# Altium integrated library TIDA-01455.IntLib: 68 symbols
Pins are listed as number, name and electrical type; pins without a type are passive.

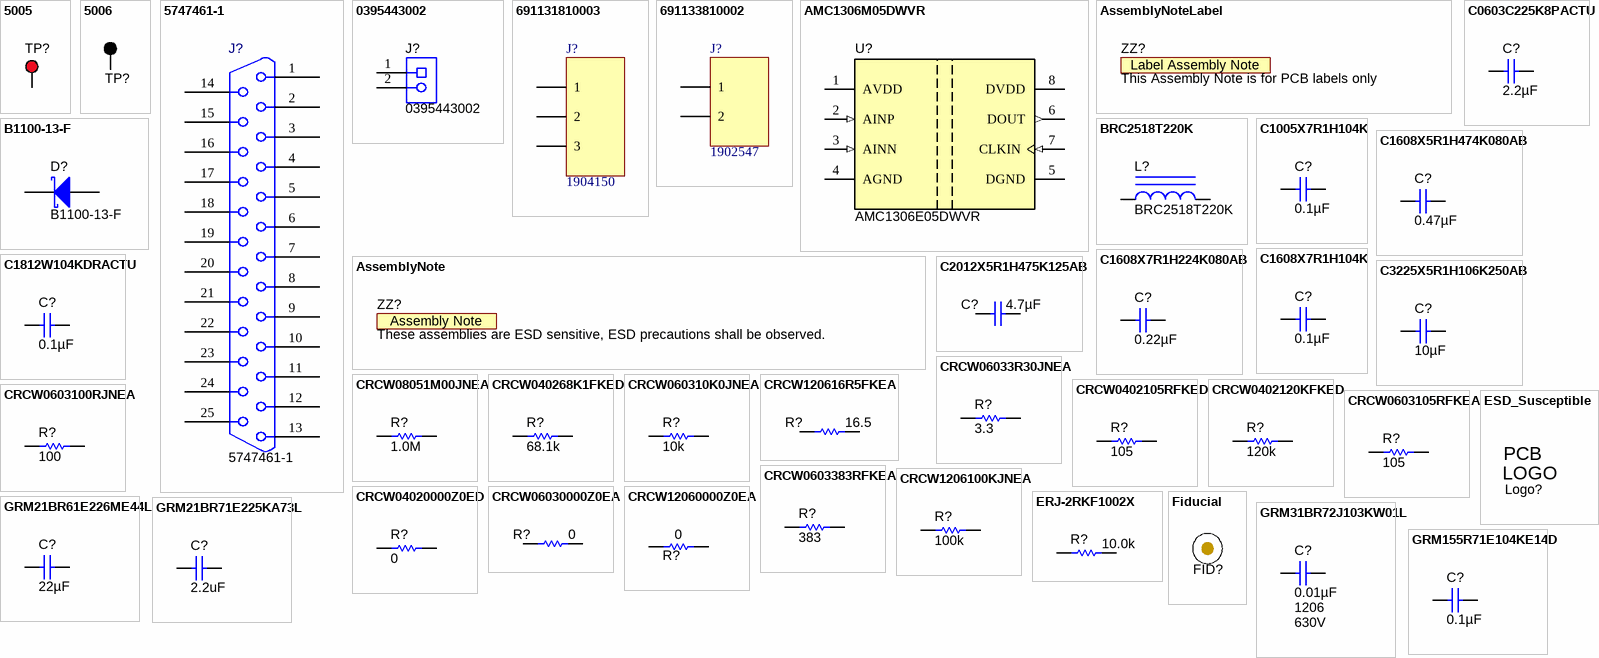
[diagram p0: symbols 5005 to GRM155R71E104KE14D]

## 5005
designator TP?  (value not drawn)
Test Point, Compact, Red, TH; Manufacturer: Keystone; CompType: Test Point Loop; ContactFinish: Silver
footprint Keystone5005
pins: 1

## 5006
designator TP?  (value not drawn)
Test Point, Compact, Black, TH; Manufacturer: Keystone; CompType: Test Point Loop; ContactFinish: Silver
footprint Keystone5006
pins: 1

## 5747461-1
designator J?
Connector, TH, DB25 parallel port, plastic, right angle; Manufacturer: AMP
footprint Amp_DB25 (Amp 5747461-1)
pins: 1, 2, 3, 4, 5, 6, 7, 8, 9, 10, 11, 12, 13, 14, 15, 16, 17, 18, 19, 20, 21, 22, 23, 24, 25

## 0395443002
designator J?
Terminal Block, 5.08mm, 2x1, TH; Manufacturer: Molex; SymbolCreator: a0412235; Pitch_mm: 5.08; Gender: Female; Row_Count: 1; Current_A: 15; Voltage_V: 300
footprint Molex_0395443002
pins: 1, 2

## 691131810003
designator J?, comment 1904150
Horizontal Cable Entry with Pressure Clamp, Serie 1318 - 10.00 mm; Manufacturer: Phoenix Contact; ComponentLink1 Description: Manufacturer; NoPins: 3
footprint PHOENIX_1902547 (CONN, PCB TERMINAL BLOCK, 9.52 MM PITCH, 3POS, TH)
pins: 1, 2, 3

## 691133810002
designator J?, comment 1902547
Horizontal Cable Entry with Pressure Clamp, Serie 1338 - 10.00 mm; Manufacturer: Phoenix Contact; ComponentLink1 Description: Manufacturer; ComponentLink2 Description: Datasheet; NoPins: 2
footprint PHOENIX_1902547 (CONN, PCB TERMINAL BLOCK, 9.52 MM PITCH, 2POS, TH)
pins: 1, 2

## AMC1306M05DWVR
designator U?, comment AMC1306E05DWVR
Small, High-Precision, Reinforced Isolated Delta-Sigma Modulator with Manchester Coded Output, DWV0008A; Alternate PartNumber: AMC1306M05DWV; Manufacturer: Texas Instruments; SymbolCreator: Altium; SizeArea_mm2: 67.275; SizeAreaWB_mm2: 105.975; SizeX_mm: 11.5; SizeY_mm: 5.85; SizeZ_mm: 2.8; CompType: IC; U/M: EA
footprint DWV0008A
pins: 1 AVDD (power), 2 AINP (in), 3 AINN (in), 4 AGND (power), 5 DGND (power), 6 DOUT (out), 7 CLKIN (in), 8 DVDD (power)

## AssemblyNote
designator ZZ?, comment These assemblies are ESD sensitive, ESD precautions shall be observed.  (no BOM)
SymbolCreator: codlsc; CompType: AssemblyNote
footprint AssemblyNote

## AssemblyNoteLabel
designator ZZ?, comment This Assembly Note is for PCB labels only  (no BOM)
SymbolCreator: a0412235
footprint AssemblyNoteLabel

## B1100-13-F
designator D?
Diode, Schottky, 100 V, 1 A, SMA; Manufacturer: Diodes Inc.; U/M: EA; Vf_V: 0.79; Value: 100V; Value1: 1A; Value2: 0.79V; Io_A: 1; Vr_V: 100; TJmax_C: 150; RJC_CperW: 25; AEC Category: Q101
signal-integrity model Diode
simulation model DI_B1100
footprint SMA
pins: 1 K, 2 A

## BRC2518T220K
designator L?
Inductor, Wirewound, 22 µH, 0.49 A, 0.56 ohm, SMD; Manufacturer: Taiyo Yuden; Value: 22uH; Ind_H: 22.0E-6; ValueDisplayed: 22µH; Imax_A: 0.49; Irms: 0.49A @ 40C rise; Isat: 0.64A @ 30% inductance drop; DCR_ohm: 0.56; Value2: 0.49A
signal-integrity model Inductor
simulation model Inductor
footprint 1007
pins: 1, 2

## C0603C225K8PACTU
designator C?  ValueDisplayed: 2.2µF  (hidden comment: C0603C225K8PACTU)
CAP, CERM, 2.2 µF, 10 V, +/- 10%, X5R, 0603; Manufacturer: Kemet; Polarized: N; CompType: Capacitor; Value: 2.2uF; U/M: EA; Cap_F: 0.0000022; Tolerance_%: 10; Value1: Unknown; Value2: 10V; TaMin_C: -55; TaMax_C: 85; Cap_Case: 0603; SizeArea_mm2: 1.28; SizeAreaWB_mm2: 4.68; SizeX_mm: 1.6; SizeY_mm: 0.8; SizeZ_mm: 1; AEC Category: Q200
signal-integrity model Cap
simulation model Cap
footprint 0603
footprint 0603M
footprint 0603L
footprint 0603_HV
footprint 0603S
pins: 1, 2

## C1005X7R1H104K
designator C?  ValueDisplayed: 0.1µF  (hidden comment: C1005X7R1H104K)
CAP, CERM, 0.1uF, 50V, +/-10%, C0G/NP0, 0402; Manufacturer: TDK; Polarized: N; CompType: Capacitor; U/M: EA; Cap_F: 0.0000001; Tolerance_%: 10; VDC_V: 50; TaMin_C: -55; TaMax_C: 125; Cap_Case: 0402
signal-integrity model Cap
simulation model Cap
footprint 0402
footprint 0402M
footprint 0402L
pins: 1, 2

## C1608X5R1H474K080AB
designator C?  ValueDisplayed: 0.47µF  (hidden comment: C1608X5R1H474K080AB)
CAP, CERM, 0.47 µF, 50 V, +/- 10%, X5R, 0603; Manufacturer: TDK; Polarized: N; CompType: Capacitor; Value: 0.47uF; U/M: EA; Cap_F: 0.00000047; Tolerance_%: 10; ESR_ohm: 0.010974; Value1: 0.010974 ohm; VDC_V: 50; Value2: 50V; IRMS_A: 1.57483; TaMin_C: -55; TaMax_C: 85; Cap_Case: 0603; AEC Category: Q200; SizeArea_mm2: 1.28; SizeAreaWB_mm2: 4.68; SizeX_mm: 1.6; SizeY_mm: 0.8; SizeZ_mm: 1
signal-integrity model Cap
simulation model Cap
footprint 0603
footprint 0603M
footprint 0603L
footprint 0603_HV
footprint 0603S
pins: 1, 2

## C1608X7R1H104K
designator C?  ValueDisplayed: 0.1µF  (hidden comment: C1608X7R1H104K)
CAP, CERM, 0.1 µF, 50 V, +/- 10%, X7R, 0603; Manufacturer: TDK; Polarized: N; CompType: Capacitor; Value: 0.1uF; U/M: EA; Cap_F: 0.0000001; Tolerance_%: 10; ESR_ohm: 0.017; Value1: 0.017 ohm; VDC_V: 50; Value2: 50V; TaMin_C: -55; TaMax_C: 125; Cap_Case: 0603; AEC Category: Q200
signal-integrity model Cap
simulation model Cap
footprint 0603
footprint 0603M
footprint 0603L
footprint 0603_HV
footprint 0603S
pins: 1, 2

## C1608X7R1H224K080AB
designator C?  ValueDisplayed: 0.22µF  (hidden comment: C1608X7R1H224K080AB)
CAP, CERM, 0.22 µF, 50 V, +/- 10%, X7R, 0603; Manufacturer: TDK; Polarized: N; CompType: Capacitor; Value: 0.22uF; U/M: EA; Cap_F: 0.00000022; Tolerance_%: 10; Value1: Unknown; VDC_V: 50; Value2: 50V; TaMin_C: -55; TaMax_C: 125; Cap_Case: 0603; AEC Category: Q200
signal-integrity model Cap
simulation model Cap
footprint 0603
footprint 0603M
footprint 0603L
footprint 0603_HV
footprint 0603S
pins: 1, 2

## C1812W104KDRACTU
designator C?  ValueDisplayed: 0.1µF  (hidden comment: C1812W104KDRACTU)
CAP, CERM, 0.1 µF, 1000 V, +/- 10%, X7R, 1812; Manufacturer: Kemet; Polarized: N; CompType: Capacitor; Value: 0.1uF; U/M: EA; Cap_F: 0.0000001; Tolerance_%: 10; Value1: Unknown; VDC_V: 1000; Value2: 1000V; TaMin_C: -55; TaMax_C: 125; Cap_Case: 1812; AEC Category: Q200
signal-integrity model Cap
simulation model Cap
footprint 1812_254
pins: 1, 2

## C2012X5R1H475K125AB
designator C?  ValueDisplayed: 4.7µF  (hidden comment: C2012X5R1H475K125AB)
CAP, CERM, 4.7 µF, 50 V, +/- 10%, X5R, 0805; Manufacturer: TDK; Polarized: N; CompType: Capacitor; Value: 4.7uF; U/M: EA; Cap_F: 0.0000047; Tolerance_%: 10; Value1: Unknown; VDC_V: 50; Value2: 50V; TaMin_C: -55; TaMax_C: 85; Cap_Case: 0805; AEC Category: Q200
signal-integrity model Cap
simulation model Cap
footprint 0805_HV
footprint 0805_HV1
footprint 0805
footprint 0805M
footprint 0805L
pins: 1, 2

## C3225X5R1H106K250AB
designator C?  ValueDisplayed: 10µF  (hidden comment: C3225X5R1H106K250AB)
CAP, CERM, 10 µF, 50 V, +/- 10%, X5R, 1210; Manufacturer: TDK; Polarized: N; CompType: Capacitor; Value: 10uF; U/M: EA; Cap_F: 0.00001; Tolerance_%: 10; Value1: Unknown; VDC_V: 50; Value2: 50V; TaMin_C: -55; TaMax_C: 85; Cap_Case: 1210; AEC Category: Q200
signal-integrity model Cap
simulation model Cap
footprint 1210_280
pins: 1, 2

## CRCW06033R30JNEA
designator R?  ValueDisplayed: 3.3  (hidden comment: CRCW06033R30JNEA)
RES, 3.3, 5%, 0.1 W, 0603; Manufacturer: Vishay-Dale; CompType: Resistor; Value: 3.3; Value_Code: 3R30; Tolerance_%: 5; Power_W: 0.1; Value2: 0.1W; VDC_V: 75; TempCo: 200 ppm/C; SizeArea_mm2: 1.28; SizeX_mm: 1.6; SizeY_mm: 0.8; SizeZ_mm: 1; EIA_Code: E24; U/M: EA; AEC Category: Q200
signal-integrity model Resistor
simulation model Resistor
footprint 0603
footprint 0603M
footprint 0603L
footprint 0603_HV
footprint 0603S
pins: 1, 2

## CRCW08051M00JNEA
designator R?  ValueDisplayed: 1.0M  (hidden comment: CRCW08051M00JNEA)
RES, 1.0 M, 5%, 0.125 W, 0805; Manufacturer: Vishay-Dale; CompType: Resistor; Value: 1.0Meg; Res_ohm: 1000000; Value_Code: 1M00; Tolerance_%: 5; Power_W: 0.125; Value2: 0.125W; VDC_V: 150; TempCo: 200 ppm/C; SizeArea_mm2: 2.5; SizeX_mm: 2; SizeY_mm: 1.25; SizeZ_mm: 1.45; EIA_Code: E24; U/M: EA; AEC Category: Q200
signal-integrity model Resistor
simulation model Resistor
footprint 0805_HV
footprint 0805_HV1
footprint 0805
footprint 0805M
footprint 0805L
pins: 1, 2

## CRCW040268K1FKED
designator R?  ValueDisplayed: 68.1k  (hidden comment: CRCW040268K1FKED)
RES, 68.1 k, 1%, 0.063 W, 0402; Manufacturer: Vishay-Dale; CompType: Resistor; Value: 68.1k; Res_ohm: 68100; Value_Code: 68k1; Tolerance_%: 1; Power_W: 0.063; Value2: 0.063W; VDC_V: 50; TempCo: 100 ppm/C; EIA_Code: E96; U/M: EA; AEC Category: Q200
signal-integrity model Resistor
simulation model Resistor
footprint 0402
footprint 0402M
footprint 0402L
footprint 0402S
pins: 1, 2

## CRCW060310K0JNEA
designator R?  ValueDisplayed: 10k  (hidden comment: CRCW060310K0JNEA)
RES, 10 k, 5%, 0.1 W, 0603; Manufacturer: Vishay-Dale; CompType: Resistor; Value: 10k; Res_ohm: 10000; Value_Code: 10k0; Tolerance_%: 5; Power_W: 0.1; Value2: 0.1W; VDC_V: 75; TempCo: 200 ppm/C; EIA_Code: E24; U/M: EA; AEC Category: Q200
signal-integrity model Resistor
simulation model Resistor
footprint 0603
footprint 0603M
footprint 0603L
footprint 0603_HV
footprint 0603S
pins: 1, 2

## CRCW120616R5FKEA
designator R?  ValueDisplayed: 16.5  (hidden comment: CRCW120616R5FKEA)
RES, 16.5, 1%, 0.25 W, 1206; Manufacturer: Vishay-Dale; CompType: Resistor; Value: 16.5; Value_Code: 16R5; Tolerance_%: 1; Power_W: 0.25; Value2: 0.25W; VDC_V: 200; TempCo: 100 ppm/C; EIA_Code: E96; U/M: EA; AEC Category: Q200; SizeArea_mm2: 5.12; SizeX_mm: 3.2; SizeY_mm: 1.6; SizeZ_mm: 1.35
signal-integrity model Resistor
simulation model Resistor
footprint 1206
footprint 1206M
footprint 1206L
pins: 1, 2

## CRCW0402105RFKED
designator R?  ValueDisplayed: 105  (hidden comment: CRCW0402105RFKED)
RES, 105, 1%, 0.063 W, 0402; Manufacturer: Vishay-Dale; CompType: Resistor; Value: 105; Value_Code: 105R; Tolerance_%: 1; Power_W: 0.063; Value2: 0.063W; VDC_V: 50; TempCo: 100 ppm/C; EIA_Code: E96; U/M: EA; AEC Category: Q200; SizeArea_mm2: 0.5; SizeZ_mm: 0.6
signal-integrity model Resistor
simulation model Resistor
footprint 0402
footprint 0402M
footprint 0402L
footprint 0402S
pins: 1, 2

## CRCW0402120KFKED
designator R?  ValueDisplayed: 120k  (hidden comment: CRCW0402120KFKED)
RES, 120 k, 1%, 0.063 W, 0402; Manufacturer: Vishay-Dale; CompType: Resistor; Value: 120k; Res_ohm: 120000; Tolerance_%: 1; Power_W: 0.063; Value2: 0.063W; VDC_V: 50; TempCo: 100 ppm/C; U/M: EA; AEC Category: Q200; SizeArea_mm2: 0.5; SizeZ_mm: 0.6
signal-integrity model Resistor
simulation model Resistor
footprint 0402
footprint 0402M
footprint 0402L
footprint 0402S
pins: 1, 2

## CRCW0603100RJNEA
designator R?  ValueDisplayed: 100  (hidden comment: CRCW0603100RJNEA)
RES, 100, 5%, 0.1 W, 0603; Manufacturer: Vishay-Dale; CompType: Resistor; Value: 100; Value_Code: 100R; Tolerance_%: 5; Power_W: 0.1; Value2: 0.1W; VDC_V: 75; TempCo: 200 ppm/C; SizeArea_mm2: 1.28; SizeX_mm: 1.6; SizeY_mm: 0.8; SizeZ_mm: 1; EIA_Code: E24; U/M: EA; AEC Category: Q200
signal-integrity model Resistor
simulation model Resistor
footprint 0603
footprint 0603M
footprint 0603L
footprint 0603_HV
footprint 0603S
pins: 1, 2

## CRCW0603105RFKEA
designator R?  ValueDisplayed: 105  (hidden comment: CRCW0603105RFKEA)
RES, 105, 1%, 0.1 W, 0603; Manufacturer: Vishay-Dale; CompType: Resistor; Value: 105; Value_Code: 105R; Tolerance_%: 1; Power_W: 0.1; Value2: 0.1W; VDC_V: 75; TempCo: 100 ppm/C; SizeArea_mm2: 1.28; SizeX_mm: 1.6; SizeY_mm: 0.8; EIA_Code: E96; U/M: EA; AEC Category: Q200
signal-integrity model Resistor
simulation model Resistor
footprint 0603
footprint 0603M
footprint 0603L
footprint 0603_HV
footprint 0603S
pins: 1, 2

## CRCW0603383RFKEA
designator R?  ValueDisplayed: 383  (hidden comment: CRCW0603383RFKEA)
RES, 383, 1%, 0.1 W, 0603; Manufacturer: Vishay-Dale; CompType: Resistor; Value: 383; Value_Code: 383R; Tolerance_%: 1; Power_W: 0.1; Value2: 0.1W; VDC_V: 75; TempCo: 100 ppm/C; SizeArea_mm2: 1.28; SizeX_mm: 1.6; SizeY_mm: 0.8; EIA_Code: E96; U/M: EA; AEC Category: Q200
signal-integrity model Resistor
simulation model Resistor
footprint 0603
footprint 0603M
footprint 0603L
footprint 0603_HV
footprint 0603S
pins: 1, 2

## CRCW1206100KJNEA
designator R?  ValueDisplayed: 100k  (hidden comment: CRCW1206100KJNEA)
RES, 100 k, 5%, 0.25 W, 1206; Manufacturer: Vishay-Dale; CompType: Resistor; Value: 100k; Res_ohm: 100000; Tolerance_%: 5; Power_W: 0.25; Value2: 0.25W; VDC_V: 200; TempCo: 200 ppm/C; EIA_Code: E24; U/M: EA; AEC Category: Q200
signal-integrity model Resistor
simulation model Resistor
footprint 1206
footprint 1206M
footprint 1206L
pins: 1, 2

## CRCW04020000Z0ED
designator R?  ValueDisplayed: 0  (hidden comment: CRCW04020000Z0ED)
RES, 0, 5%, 0.063 W, 0402; Manufacturer: Vishay-Dale; CompType: Resistor; Value: 0; Value_Code: 0000; Tolerance_%: 5; Power_W: 0.063; Value2: 0.063W; VDC_V: 50; TempCo: 200 ppm/C; EIA_Code: E24; U/M: EA; AEC Category: Q200; SizeArea_mm2: 0.5; SizeX_mm: 1; SizeZ_mm: 0.6
signal-integrity model Resistor
simulation model Resistor
footprint 0402
footprint 0402M
footprint 0402L
footprint 0402S
pins: 1, 2

## CRCW06030000Z0EA
designator R?  ValueDisplayed: 0  (hidden comment: CRCW06030000Z0EA)
RES, 0, 5%, 0.1 W, 0603; Manufacturer: Vishay-Dale; CompType: Resistor; Value: 0; Value_Code: 0000; Tolerance_%: 5; Power_W: 0.1; Value2: 0.1W; VDC_V: 75; TempCo: 200 ppm/C; EIA_Code: E24; U/M: EA; AEC Category: Q200; SizeArea_mm2: 1.28; SizeX_mm: 1.6; SizeY_mm: 0.8; SizeZ_mm: 1
signal-integrity model Resistor
simulation model Resistor
footprint 0603
footprint 0603M
footprint 0603L
footprint 0603_HV
footprint 0603S
pins: 1, 2

## CRCW12060000Z0EA
designator R?  ValueDisplayed: 0  (hidden comment: CRCW12060000Z0EA)
RES, 0, 5%, 0.25 W, 1206; Manufacturer: Vishay-Dale; CompType: Resistor; Value: 0; Value_Code: 0000; Tolerance_%: 5; Power_W: 0.25; Value2: 0.25W; VDC_V: 200; TempCo: 200 ppm/C; EIA_Code: E24; U/M: EA; AEC Category: Q200; SizeArea_mm2: 5.12; SizeX_mm: 3.2; SizeY_mm: 1.6; SizeZ_mm: 1.35
signal-integrity model Resistor
simulation model Resistor
footprint 1206
footprint 1206M
footprint 1206L
pins: 1, 2

## ERJ-2RKF1002X
designator R?  ValueDisplayed: 10.0k  (hidden comment: ERJ-2RKF1002X)
RES, 10.0 k, 1%, 0.1 W, 0402; Manufacturer: Panasonic; CompType: Resistor; Value: 10.0k; Res_ohm: 10000; Value_Code: 10k0; Tolerance_%: 1; Power_W: 0.1; Value2: 0.1W; VDC_V: 50; TempCo: 100 ppm/C; EIA_Code: E96; U/M: EA; AEC Category: Q200
signal-integrity model Resistor
simulation model Resistor
footprint 0402
footprint 0402M
footprint 0402L
footprint 0402S
pins: 1, 2

## ESD_Susceptible
designator Logo?, comment ESD Susceptible  (value not drawn)  (no BOM)
ESD Susceptible Symbol; SymbolCreator: a0412235
footprint ESD_Overlay_Large
footprint ESD_Overlay_Medium
footprint ESD_Overlay_Small

## Fiducial
designator FID?  (value not drawn)
Fiducial mark.  There is nothing to buy or mount.; SymbolCreator: codlsc
footprint Fiducial10-30
footprint Fiducial10-20
footprint Fiducial15-30
footprint Fiducial20-40
footprint Fiducial6.4-20

## GRM21BR61E226ME44L
designator C?  ValueDisplayed: 22µF  (hidden comment: GRM21BR61E226ME44L)
CAP, CERM, 22 µF, 25 V, +/- 20%, X5R, 0805; Manufacturer: MuRata; Polarized: N; CompType: Capacitor; Value: 22uF; U/M: EA; Cap_F: 0.000022; Tolerance_%: 20; Value1: Unknown; VDC_V: 25; Value2: 25V; TaMin_C: -55; TaMax_C: 85; Cap_Case: 0805; AEC Category: Q200
signal-integrity model Cap
simulation model Cap
footprint 0805_HV
footprint 0805_HV1
footprint 0805
footprint 0805M
footprint 0805L
pins: 1, 2

## GRM21BR71E225KA73L
designator C?  ValueDisplayed: 2.2uF  (hidden comment: GRM21BR71E225KA73L)
CAP, CERM, 2.2uF, 25V, +/-10%, X7R, 0805; Manufacturer: MuRata; Polarized: N; CompType: Capacitor; U/M: EA; Cap_F: 0.0000022; Tolerance_%: 10; ESR_Ohm: 0.005; Value1: 0.005 ohm; VDC_V: 25; TaMin_C: -55; TaMax_C: 125; Cap_Case: 0805
signal-integrity model Cap
simulation model Cap
footprint 0805_HV
footprint 0805
footprint 0805M
footprint 0805L
pins: 1, 2

## GRM31BR72J103KW01L
designator C?  ValueDisplayed: 0.01µF  PackageReference: 1206  Value2: 630V  (hidden comment: GRM31BR72J103KW01L)
CAP, CERM, 0.01uF, 630V, +/-10%, X7R, 1206; Manufacturer: MuRata; Polarized: N; CompType: Capacitor; U/M: EA; Cap_F: 0.00000001; Tolerance_%: 10; Value1: Unknown; VDC_V: 630; TaMin_C: -55; TaMax_C: 125
signal-integrity model Cap
simulation model Cap
footprint 1206
footprint 1206M
footprint 1206L
pins: 1, 2

## GRM155R71E104KE14D
designator C?  ValueDisplayed: 0.1µF  (hidden comment: GRM155R71E104KE14D)
CAP, CERM, 0.1 µF, 25 V, +/- 10%, X7R, 0402; Manufacturer: MuRata; Polarized: N; CompType: Capacitor; Value: 0.1uF; U/M: EA; Cap_F: 0.0000001; Tolerance_%: 10; Value1: Unknown; VDC_V: 25; Value2: 25V; TaMin_C: -55; TaMax_C: 125; Cap_Case: 0402; AEC Category: Q200
signal-integrity model Cap
simulation model Cap
footprint 0402
footprint 0402M
footprint 0402L
footprint 0402S
pins: 1, 2

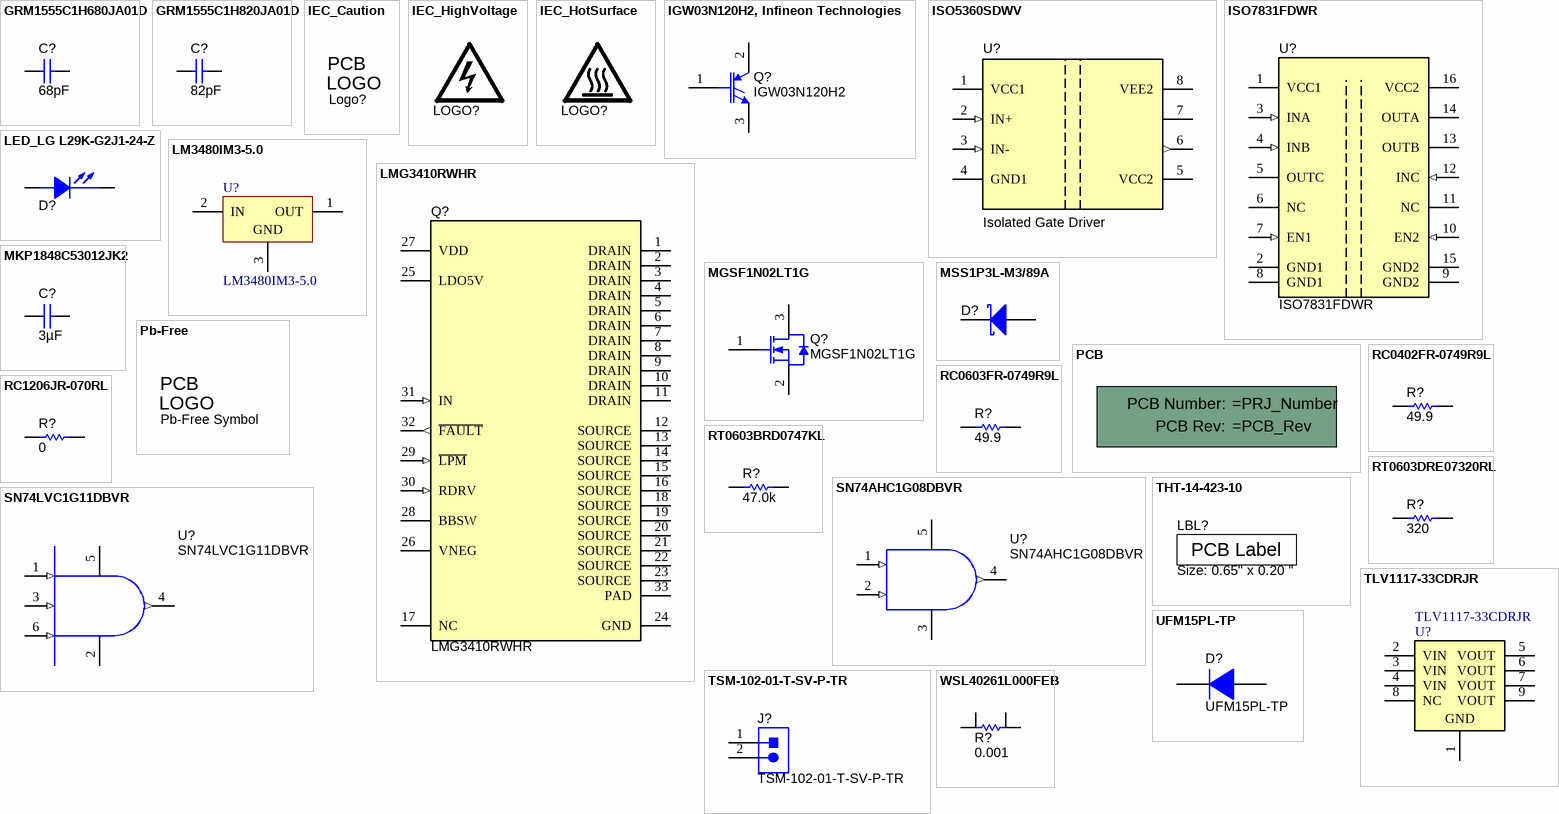
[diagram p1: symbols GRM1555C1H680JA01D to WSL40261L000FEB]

## GRM1555C1H680JA01D
designator C?  ValueDisplayed: 68pF  (hidden comment: GRM1555C1H680JA01D)
CAP, CERM, 68 pF, 50 V, +/- 5%, C0G/NP0, 0402; Manufacturer: MuRata; Polarized: N; CompType: Capacitor; Value: 68pF; U/M: EA; Cap_F: 0.000000000068; Tolerance_%: 5; Value1: Unknown; VDC_V: 50; Value2: 50V; TaMin_C: -55; TaMax_C: 125; Cap_Case: 0402; AEC Category: Q200
signal-integrity model Cap
simulation model Cap
footprint 0402
footprint 0402M
footprint 0402L
footprint 0402S
pins: 1, 2

## GRM1555C1H820JA01D
designator C?  ValueDisplayed: 82pF  (hidden comment: GRM1555C1H820JA01D)
CAP, CERM, 82 pF, 50 V, +/- 5%, C0G/NP0, 0402; Manufacturer: MuRata; Polarized: N; CompType: Capacitor; Value: 82pF; U/M: EA; Cap_F: 0.000000000082; Tolerance_%: 5; Value1: Unknown; VDC_V: 50; Value2: 50V; TaMin_C: -55; TaMax_C: 125; Cap_Case: 0402; SizeArea_mm2: 0.5; SizeAreaWB_mm2: 3; SizeX_mm: 1; SizeZ_mm: 0.6; AEC Category: Q200
signal-integrity model Cap
simulation model Cap
footprint 0402
footprint 0402M
footprint 0402L
footprint 0402S
pins: 1, 2

## IEC_Caution
designator Logo?, comment CAUTION.  READ USER GUIDE BEFORE USE  (value not drawn)  (no BOM)
IEC 61010-1 Caution Warning; SymbolCreator: a0412235
footprint IEC_Caution_small
footprint IEC_Caution_Medium
footprint IEC_Caution_Small

## IEC_HighVoltage
designator LOGO?, comment DANGER HIGH VOLTAGE  (value not drawn)  (no BOM)
IEC 61010-1 High Voltage Warning; SymbolCreator: a0412235
footprint IEC_HighVoltage_medium
footprint IEC_HighVoltage_Medium
footprint IEC_HighVoltage_Small

## IEC_HotSurface
designator LOGO?, comment CAUTION HOT SURFACE  (value not drawn)  (no BOM)
IEC 61010-1 Hot Surface Warning; SymbolCreator: a0412235
footprint IEC_HotSurface_Medium
footprint IEC_HotSurface_Medium
footprint IEC_HotSurface_Small

## IGW03N120H2, Infineon Technologies
designator Q?, comment IGW03N120H2
Transistor, IGBT, 1200 V, 9.9 A, TO-247; Manufacturer: Infineon Technologies; SymbolCreator: Altium; PNP: 0; Vceo_V: 1200; Vcesat1_V: 2.8; Value: 1200 V; IcRated_A: 9.6; Value1: 9.6 A; TaMin_C: -40; TaMax_C: 150; CompType: BJT; U/M: EA; AEC Category: Q101
footprint TO-247
pins: 1 G, 2 C, 3 E

## ISO5360SDWV
designator U?, comment Isolated Gate Driver
0.5/2/4/6A/10A Isolated IGBT Gate Drivers with High CMTI, DWV0008A; Manufacturer: Texas Instruments; SymbolCreator: Altium; SizeArea_mm2: 67.275; SizeAreaWB_mm2: 105.975; SizeX_mm: 11.5; SizeY_mm: 5.85; SizeZ_mm: 2.8; CompType: IC; U/M: EA
footprint SOIC_ISO5360MD
pins: 1 VCC1 (power), 2 IN+ (in), 3 IN- (in), 4 GND1 (power), 5 VCC2 (power), 6 OUT (out), 7 GND2 (power), 8 VEE2 (power)

## ISO7831FDWR
designator U?
High-Performance, 8000 VPK Reinforced Triple Digital Isolator, DW0016B; Manufacturer: Texas Instruments; SymbolCreator: Altium; CompType: IC; U/M: EA
footprint DW0016B_N
footprint DW0016B_M
footprint DW0016B_L
footprint DW0016B_HV
pins: 1 VCC1 (power), 2 GND1 (power), 3 INA (in), 4 INB (in), 5 OUTC (hiz), 6 NC, 7 EN1 (in), 8 GND1 (power), 9 GND2 (power), 10 EN2 (in), 11 NC, 12 INC (in), 13 OUTB (hiz), 14 OUTA (hiz), 15 GND2 (power), 16 VCC2 (power)

## LED_LG L29K-G2J1-24-Z
designator D?
LED SmartLED Green 570NM; PartNumber: LG L29K-G2J1-24-Z; Manufacturer: OSRAM; SymbolCreator: x0120606
footprint LED0603AA
pins: 1 C, 2 A

## LM3480IM3-5.0
designator U?
100 mA, Quasi Low-Dropout Linear Voltage Regulator, 3-pin SOT-23; Manufacturer: Texas Instruments; PackageTopMarking: L0B*XTT; PowerWise: N; CompType: LDO IC
footprint MF03A_N (SOT23, 3-Leads, Body 2.9x1.3mm, Pitch 0.95mm, Lead Span 2.4mm, IPC Medium Density)
footprint MF03A_L (SOT23, 3-Leads, Body 2.9x1.3mm, Pitch 0.95mm, Lead Span 2.4mm, IPC High Density)
footprint MF03A_M (SOT23, 3-Leads, Body 2.9x1.3mm, Pitch 0.95mm, Lead Span 2.4mm, IPC Low Density)
pins: 1 OUT (power), 2 IN (power), 3 GND (power)

## LMG3410RWHR
designator Q?
600-V 12-A Single Channel GaN Power Stage, RWH0032A; Alternate PartNumber: LMG3410RWHT; Manufacturer: Texas Instruments; SymbolCreator: Altium; CompType: IC; U/M: EA
footprint RWH0032A_NV (VQFN, 32-Lead, Body 8x8mm)
pins: 1 DRAIN, 2 DRAIN, 3 DRAIN, 4 DRAIN, 5 DRAIN, 6 DRAIN, 7 DRAIN, 8 DRAIN, 9 DRAIN, 10 DRAIN, 11 DRAIN, 12 SOURCE, 13 SOURCE, 14 SOURCE, 15 SOURCE, 16 SOURCE, 17 NC, 18 SOURCE, 19 SOURCE, 20 SOURCE, 21 SOURCE, 22 SOURCE, 23 SOURCE, 24 GND (power), 25 LDO5V (power), 26 VNEG (power), 27 VDD (power), 28 BBSW (power), 29 ~{LPM} (in), 30 RDRV (in), 31 IN (in), 32 ~{FAULT} (out), 33 PAD (power)

## MGSF1N02LT1G
designator Q?
MOSFET, N-CH, 20 V, 0.75 A, SOT-23; Manufacturer: ON Semiconductor; Alternate Manufacturer: None; U/M: EA; ChType: N; Value: 20V; VdsMax_V: 20; Value1: 0.13 ohm; Rdson45_ohm: 0.13; Value2: 6 nC; QgTyp_nC: 6; IdsMax_A: 0.75
footprint SOT-23
footprint SOT-23M
footprint SOT-23L
pins: 1 G, 2 S, 3 D

## MKP1848C53012JK2
designator C?  ValueDisplayed: 3µF  (hidden comment: MKP1848C53012JK2)
CAP, Film, 3 µF, 1200 V, +/- 5%, 0.015 ohm, TH; Manufacturer: Vishay-Bccomponents; Polarized: N; CompType: Capacitor; Value: 3uF; U/M: EA; Cap_F: 0.000003; Tolerance_%: 5; VDC_V: 1200; Value2: 1200V; ESR_ohm: 0.015; IRMS_A: 6; TaMin_C: -55; TaMax_C: 105; Cap_Case: 32x18x28; SizeAreaWB_mm2: 680; SizeArea_mm2: 576; SizeX_mm: 32; SizeY_mm: 18; SizeZ_mm: 28; AEC Category: Q200
signal-integrity model Cap
simulation model Cap
footprint MKP1848Cx2_3200x1800x2800
pins: 1, 2

## MSS1P3L-M3/89A
designator D?, comment MSS2P3-M3/89A  (value not drawn)
Diode, Schottky, 30 V, 2 A, AEC-Q101, MicroSMP; Manufacturer: Vishay-Semiconductor; U/M: EA; Vf_V: 0.6; Value: 30V; Value1: 2A; Value2: 0.6V; Io_A: 1; Vr_V: 30; TJmax_C: 150; RJC_CperW: 40; AEC Category: Q101; AEC Qualified: Y
signal-integrity model Diode
footprint MicroSMP
pins: 1 K, 2 A

## Pb-Free
designator Logo?, comment Pb-Free Symbol  (no BOM)
SymbolCreator: a0412235
footprint Pb-Free_Overlay_Medium
footprint Pb-Free_Overlay_Small

## PCB
designator !PCB?, comment Printed Circuit Board  (value not drawn)  (mechanical)
Manufacturer: Any; SymbolCreator: a0412235; CompType: PCB
1 alternate drawing of the same symbol

## RC0402FR-0749R9L
designator R?  ValueDisplayed: 49.9  (hidden comment: RC0402FR-0749R9L)
RES, 49.9, 1%, 0.063 W, 0402; Manufacturer: Yageo America; CompType: Resistor; Value: 49.9; Value_Code: 49R9; Tolerance_%: 1; Power_W: 0.063; Value2: 0.063W; VDC_V: 50; TempCo: 100 ppm/C; EIA_Code: E96; U/M: EA; AEC Category: Q200; AEC Qualified: N
signal-integrity model Resistor
simulation model Resistor
footprint 0402
footprint 0402M
footprint 0402L
footprint 0402S
pins: 1, 2

## RC0603FR-0749R9L
designator R?  ValueDisplayed: 49.9  (hidden comment: RC0603FR-0749R9L)
RES, 49.9, 1%, 0.1 W, 0603; Manufacturer: Yageo America; CompType: Resistor; Value: 49.9; Value_Code: 49R9; Tolerance_%: 1; Power_W: 0.1; Value2: 0.1W; VDC_V: 150; TempCo: 200 ppm/C; EIA_Code: E96; U/M: EA; AEC Category: Q200
signal-integrity model Resistor
simulation model Resistor
footprint 0603
footprint 0603M
footprint 0603L
footprint 0603_HV
footprint 0603S
pins: 1, 2

## RC1206JR-070RL
designator R?  ValueDisplayed: 0  (hidden comment: RC1206JR-070RL)
RES, 0, 5%, 0.25 W, 1206; Manufacturer: Yageo America; CompType: Resistor; Value: 0; Value_Code: 0000; Tolerance_%: 5; Power_W: 0.25; Value2: 0.25W; VDC_V: 200; TempCo: 200 ppm/C; SizeArea_mm2: 5.12; SizeX_mm: 3.2; SizeY_mm: 1.6; SizeZ_mm: 1.35; EIA_Code: E24; U/M: EA; AEC Category: Q200
signal-integrity model Resistor
simulation model Resistor
footprint 1206
footprint 1206M
footprint 1206L
pins: 1, 2

## RT0603BRD0747KL
designator R?  ValueDisplayed: 47.0k  (hidden comment: RT0603BRD0747KL)
RES, 47.0 k, 0.1%, 0.1 W, 0603; Manufacturer: Yageo America; CompType: Resistor; Value: 47.0k; Res_ohm: 47000; Value_Code: 47k0; Tolerance_%: 0.1; Value2: 0.1W; VDC_V: 75; TempCo: 25 ppm/C; EIA_Code: E192; U/M: EA; AEC Category: Q200; SizeArea_mm2: 1.28; SizeX_mm: 1.6; SizeY_mm: 0.8; SizeZ_mm: 1
signal-integrity model Resistor
simulation model Resistor
footprint 0603
footprint 0603M
footprint 0603L
footprint 0603_HV
footprint 0603S
pins: 1, 2

## RT0603DRE07320RL
designator R?  ValueDisplayed: 320  (hidden comment: RT0603DRE07320RL)
RES, 320, 0.5%, 0.1 W, 0603; Manufacturer: Yageo America; CompType: Resistor; Value: 320; Value_Code: 320R; Tolerance_%: 0.5; Power_W: 0.1; Value2: 0.1W; VDC_V: 75; TempCo: 50 ppm/C; SizeArea_mm2: 1.28; SizeX_mm: 1.6; SizeY_mm: 0.8; SizeZ_mm: 1; EIA_Code: E192; U/M: EA; AEC Category: Q200
signal-integrity model Resistor
simulation model Resistor
footprint 0603
footprint 0603M
footprint 0603L
footprint 0603_HV
footprint 0603S
pins: 1, 2

## SN74AHC1G08DBVR
designator U?
Single 2-Input Positive-AND Gate, DBV0005A; Alternate PartNumber: SN74AHC1G08DBVT; Manufacturer: Texas Instruments; CompType: IC; SizeArea_mm2: 8.12; SizeAreaWB_mm2: 14.82; SizeX_mm: 2.8; SizeY_mm: 2.9; SizeZ_mm: 1.45; U/M: EA
footprint DBV0005A_N
footprint DBV0005A_M
footprint DBV0005A_L
pins: 1 A (in), 2 B (in), 3 V- (power), 4 Y (out), 5 V+ (power)

## SN74LVC1G11DBVR
designator U?
Single 3-Input Positive-AND Gate, DBV0006A; Manufacturer: Texas Instruments; SymbolVersion: Altium; SizeArea_mm2: 8.12; SizeAreaWB_mm2: 14.82; SizeX_mm: 2.8; SizeY_mm: 2.9; SizeZ_mm: 1.45; CompType: IC; U/M: EA
footprint DBV0006A_N
footprint DBV0006A_M
footprint DBV0006A_L
pins: 1 A (in), 2 GND (power), 3 B (in), 4 Y (out), 5 VCC (power), 6 C (in)

## THT-14-423-10
designator LBL?, comment Size: 0.65" x 0.20 "
Thermal Transfer Printable Labels, 0.650" W x 0.200" H - 10,000 per roll; Manufacturer: Brady; PartNumber: THT-14-423-10; SymbolCreator: a0412235; CompType: Label
footprint Label_650x200

## TLV1117-33CDRJR
designator U?
LDO with 4.7 to 15 V Input and 3.3 V Output, 0 to 125 degC, 8-Pin SON (DRJ), Green (RoHS & no Sb/Br); Manufacturer: Texas Instruments; Alternate PartNumber: Equivalent; Iout(Max)(A): 0.8; Iq(Typ)(mA): 5; SubFamily: Single Channel LDO; Vin(Max)(V): 15; Vin(Min)(V): 4.7; Vout(Max)(V): 3.3
footprint DRJ0008A (SON, 8-Leads, Body 4x4mm, Pitch 0.8mm, Thermal Pad 3x2.2mm, TI Recommended)
pins: 1 GND (power), 2 VIN (power), 3 VIN (power), 4 VIN (power), 5 VOUT (power), 6 VOUT (power), 7 VOUT (power), 8 NC, 9 VOUT (power)

## TSM-102-01-T-SV-P-TR
designator J?
Header, 100mil, 2x1, Tin, SMD; Manufacturer: Samtec; SymbolCreator: a0412235; Pitch_mm: 2.54; Gender: Male; Shrouded: N; Row_Count: 1; Current_A: 5.4; Voltage_V: 475; Cert_CSA: Y
footprint Samtec_TSM-102-01-T-SV-P-TR
pins: 1, 2
1 alternate drawing of the same symbol

## UFM15PL-TP
designator D?
Diode, Ultrafast, 600 V, 1 A, SOD-123FL; Manufacturer: Micro Commercial Components; U/M: EA; Vf_V: 1.7; Value: 600V; Value1: 1A; Value2: 1.7V; Io_A: 1; Vr_V: 600; TJmax_C: 150; AEC Category: Q101; AEC Qualified: N
signal-integrity model Diode
footprint SOD-123FL
pins: 1 K, 2 A

## WSL40261L000FEB
designator R?  ValueDisplayed: 0.001  (hidden comment: WSL40261L000FEB)
RES, 0.001, 1%, 3 W, 10.1x2.68x2.6mm; Manufacturer: Vishay-Dale; CompType: Resistor; Value: 0.001; Value_Code: 1L000; Tolerance_%: 1; Power_W: 3; Value2: 3W; TempCo: 75 ppm/C; EIA_Code: E96; U/M: EA; AEC Category: Q200
signal-integrity model Resistor
simulation model Resistor
footprint WSL4026_1milli
pins: 1, 2, 3, 4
